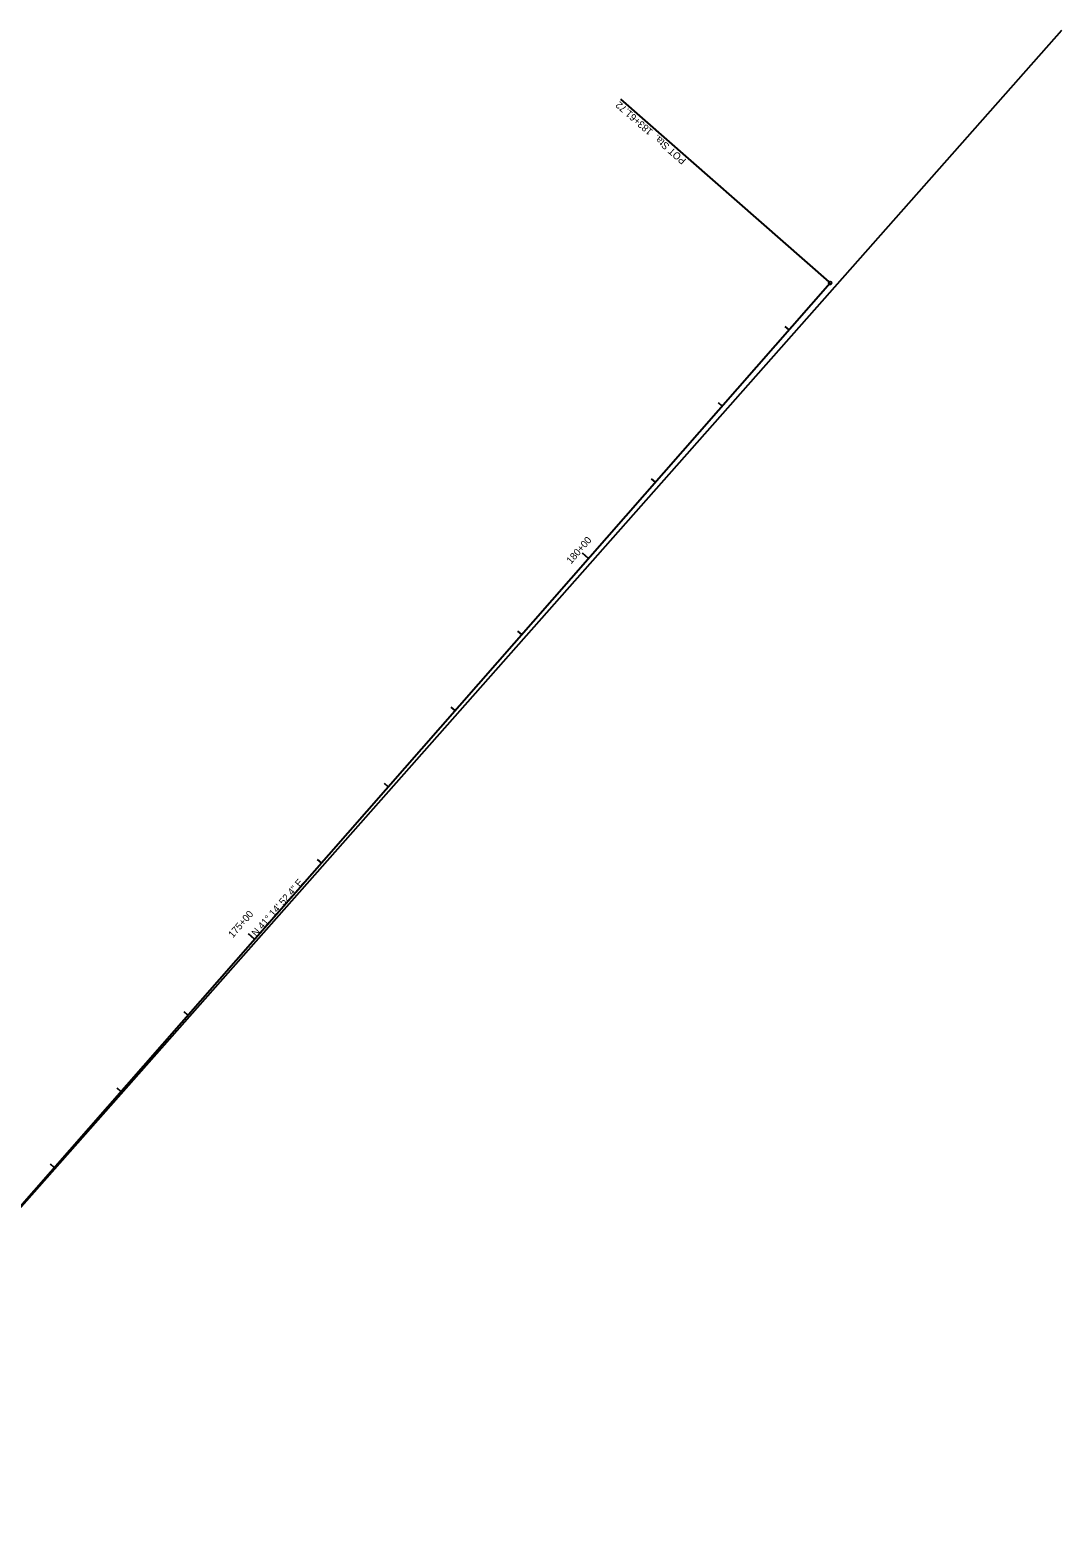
# Model space of a CAD drawing. Extents: x 1722038 to 1726172, y 967033 to 975427.
# Drawn here: x 1724897 to 1725915, y 973939 to 975427 of the extents above; entities that cross this region are included whole.
import ezdxf

# ---------------------------------------------------------------- set-up
doc = ezdxf.new("R2010")
doc.units = 0
for name, color, linetype in [('Prop Horizontal Alignment', 7, 'Continuous'), ('Prop Horizontal Alignment Direction Label', 7, 'Continuous'), ('Prop Horizontal Alignment Station Label', 7, 'Continuous'), ('Prop Horizontal Alignment Tick Label', 7, 'Continuous'), ('Prop Horizontal Alignment Tick Large', 7, 'Continuous'), ('Prop Horizontal Alignment Tick Small', 7, 'Continuous')]:
    doc.layers.add(name, color=color, linetype=linetype)

msp = doc.modelspace()

# ---------------------------------------------------------------- linework, layer by layer
at = {"layer": 'Prop Horizontal Alignment'}
for p, q in [((1724599.7, 973939.6), (1725915.1, 975427.3)), ((1724600, 973938.6), (1725686.5, 975177.7))]:
    msp.add_line(p, q, dxfattribs=at)
at = {"layer": 'Prop Horizontal Alignment Station Label'}
msp.add_line((1725685.4, 975178.7), (1725479.7, 975359), dxfattribs=at)
msp.add_circle((1725686.5, 975177.7), 1.5, dxfattribs=at)
at = {"layer": 'Prop Horizontal Alignment Tick Large'}
for p, q in [((1725448, 974905.7), (1725442, 974911)), ((1725118.4, 974529.8), (1725112.3, 974535.1))]:
    msp.add_line(p, q, dxfattribs=at)
at = {"layer": 'Prop Horizontal Alignment Tick Small'}
for p, q in [((1725645.8, 975131.3), (1725642.1, 975134.6)), ((1725579.9, 975056.1), (1725576.1, 975059.4)), ((1725513.9, 974980.9), (1725510.2, 974984.2)), ((1725382.1, 974830.5), (1725378.3, 974833.8)), ((1725316.2, 974755.4), (1725312.4, 974758.7)), ((1725250.2, 974680.2), (1725246.5, 974683.5)), ((1725184.3, 974605), (1725180.5, 974608.3)), ((1725052.4, 974454.6), (1725048.7, 974457.9)), ((1724986.5, 974379.4), (1724982.7, 974382.7)), ((1724920.6, 974304.2), (1724916.8, 974307.5))]:
    msp.add_line(p, q, dxfattribs=at)

# ---------------------------------------------------------------- texts
at = {"layer": 'Prop Horizontal Alignment Direction Label'}
msp.add_text('N 41%%d 14\' 52.4" E', height=7, rotation=48.7521, dxfattribs=at).set_placement((1725119.9, 974531.9))
at = {"layer": 'Prop Horizontal Alignment Station Label'}
msp.add_text('POT Sta.  183+61.72', height=7, rotation=138.7521, dxfattribs=at).set_placement((1725544.8, 975299.3))
at = {"layer": 'Prop Horizontal Alignment Tick Label'}
for s, p in [('180+00', (1725430.7, 974899.7)), ('175+00', (1725096.9, 974530.5))]:
    msp.add_text(s, height=7, rotation=48.7521, dxfattribs=at).set_placement(p)

doc.saveas('drawing.dxf')
